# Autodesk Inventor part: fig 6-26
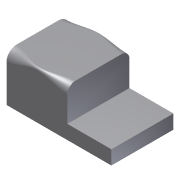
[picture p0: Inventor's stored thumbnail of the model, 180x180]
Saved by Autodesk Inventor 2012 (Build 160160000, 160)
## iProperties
Created: 2004-05
Part Number: fig 6-26
Document SubType Name: Modeling
Designer: CADCIM Technologies
Manufacturer: Standard
Standards Organization: Custom
Density: 1 g/cm^3
Material: Default
Author: CADCIM Technologies
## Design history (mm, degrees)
node "Sketch1"
sketch "Sketch2"
  geometry: L1 (0.098, 47.711)-(0.098, 0.049); L2 (0.098, 0.049)-(-105.483, 0.049); L3 (-105.483, 0.049)-(-105.483, 14.192); L4 (-105.483, 14.192)-(-61.139, 14.192); L5 (-61.139, 14.192)-(-61.139, 47.711); L6 (-61.139, 47.711)-(0.098, 47.711)
  constraints: 12 end point, 3 parallel, 2 perpendicular, 1 vertical
extrude "Extrusion1" new body sketch "Sketch2" stored distance "d0" = 62.5; taper "d1" = 0 deg
fillet "Fillet9" dims "d61" = 10, "d62" = 8, "d63" = 2, "d64" = 5
fillet "Fillet10" dims "d65" = 8, "d66" = 10, "d67" = 2, "d68" = 5
body "Solid1"
